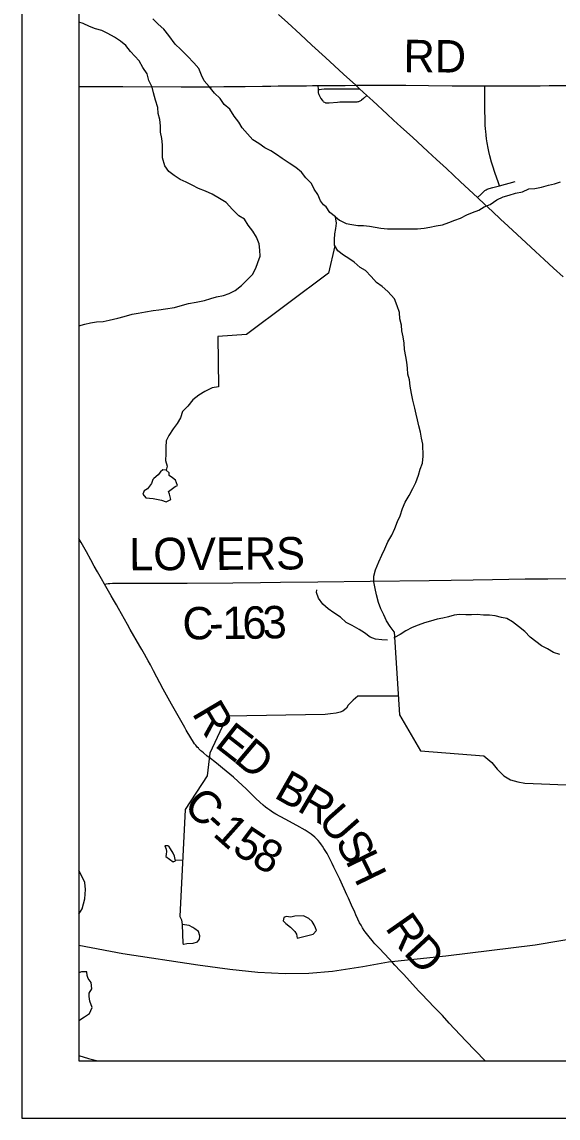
# Model space of a CAD drawing. Extents: x 0 to 34, y 0 to 22.
# Drawn here: x 23.344 to 24.284, y 13.024 to 14.945 of the extents above; entities that cross this region are included whole.
import ezdxf

# ---------------------------------------------------------------- set-up
doc = ezdxf.new("R2010")
doc.units = 0
for name, color, linetype in [('GM_X_Corporation', 7, 'Continuous'), ('GM_X_County_Road', 7, 'Continuous'), ('GM_X_County_Road_Text', 7, 'Continuous'), ('GM_X_Minor_Lake', 7, 'Continuous'), ('GM_X_Minor_River', 7, 'Continuous'), ('GM_X_Rail_Line', 7, 'Continuous'), ('GM_X_State_Route', 7, 'Continuous'), ('GM_X_Township_Road', 7, 'Continuous'), ('GM_X_Township_Road_Text', 7, 'Continuous'), ('SH_Data', 7, 'Continuous')]:
    doc.layers.add(name, color=color, linetype=linetype)

msp = doc.modelspace()

# ---------------------------------------------------------------- linework, layer by layer
at = {"layer": 'GM_X_Corporation'}
msp.add_lwpolyline([(23.4438, 15.6034), (23.4438, 13.1239), (28.8008, 13.1239)], dxfattribs=at)
at = {"layer": 'GM_X_County_Road'}
for points in [[(23.4888, 13.9594), (23.4834, 13.9688), (23.4763, 13.9812), (23.4708, 13.9909), (23.4645, 14.0023), (23.4571, 14.016), (23.4478, 14.0327), (23.4438, 14.0398)], [(23.4888, 13.9594), (23.4916, 13.9601), (23.4949, 13.9607), (23.4982, 13.961), (23.5028, 13.9612), (23.5118, 13.9614), (23.5311, 13.9615), (23.6336, 13.9613), (23.7135, 13.9616), (23.762, 13.9624), (23.7974, 13.9629), (23.8625, 13.9638), (23.9543, 13.9647), (24.0582, 13.9658), (24.1348, 13.9672), (24.1688, 13.968), (24.2264, 13.9689), (24.266, 13.9688), (24.3705, 13.9698)], [(23.966, 13.3259), (23.9629, 13.3292), (23.9599, 13.3326), (23.9585, 13.3342), (23.955, 13.3383), (23.9479, 13.3472), (23.9457, 13.35), (23.9439, 13.3525), (23.941, 13.3571), (23.9384, 13.3618), (23.936, 13.3662), (23.9328, 13.3727), (23.9293, 13.3801), (23.9273, 13.3846), (23.9219, 13.3971), (23.9163, 13.4094), (23.9137, 13.4151), (23.9012, 13.4423), (23.8973, 13.4505), (23.891, 13.4635), (23.8879, 13.4701), (23.8862, 13.4734), (23.8788, 13.4874), (23.8735, 13.4965), (23.871, 13.5003), (23.8693, 13.5028), (23.8664, 13.5066), (23.8635, 13.5102), (23.8611, 13.5127), (23.8573, 13.5164), (23.8511, 13.5217), (23.8459, 13.5252), (23.8407, 13.5285), (23.826, 13.5368), (23.8057, 13.5475), (23.7893, 13.5564), (23.7831, 13.5602), (23.7784, 13.5632), (23.7749, 13.5658), (23.7709, 13.5688), (23.7666, 13.5723), (23.7548, 13.5833), (23.7363, 13.6016), (23.7308, 13.6068), (23.7148, 13.6211), (23.6957, 13.6372), (23.685, 13.6458), (23.6714, 13.6562), (23.6687, 13.6584), (23.6623, 13.6637), (23.6593, 13.6663), (23.6577, 13.6677), (23.6555, 13.6697), (23.6541, 13.671), (23.6533, 13.6719), (23.6513, 13.6741), (23.6487, 13.6772), (23.6467, 13.68), (23.632, 13.7036), (23.6293, 13.7082), (23.6062, 13.7491), (23.5917, 13.7758), (23.5748, 13.8076), (23.569, 13.8183), (23.5652, 13.8252), (23.5621, 13.8306), (23.5586, 13.8368), (23.5539, 13.845), (23.5505, 13.8509), (23.5338, 13.88), (23.5289, 13.8887), (23.513, 13.9168), (23.5094, 13.9233), (23.5046, 13.9318), (23.5003, 13.9393), (23.4932, 13.9516), (23.4888, 13.9594)], [(23.9979, 13.2918), (23.9936, 13.2966), (23.9881, 13.3026), (23.9701, 13.3214), (23.966, 13.3259)], [(24.156, 13.1239), (24.1387, 13.1422), (24.1221, 13.1595), (24.093, 13.1904), (24.0812, 13.2035), (24.077, 13.208), (24.0665, 13.2185), (24.0449, 13.2411), (24.0398, 13.2465), (24.0232, 13.2646), (24.0134, 13.2753), (24.0072, 13.2819), (23.9979, 13.2918)]]:
    msp.add_lwpolyline(points, dxfattribs=at)
at = {"layer": 'GM_X_Minor_Lake'}
for p, q in [((23.5736, 14.1429), (23.571, 14.136)), ((23.5962, 13.4821), (23.6091, 13.4731)), ((23.6248, 13.3629), (23.6261, 13.3299)), ((23.8263, 13.3394), (23.8543, 13.3461))]:
    msp.add_line(p, q, dxfattribs=at)
for points in [[(23.571, 14.136), (23.5639, 14.1269), (23.5579, 14.1234), (23.556, 14.117), (23.561, 14.1106), (23.5742, 14.1095), (23.5883, 14.1066), (23.597, 14.104), (23.6049, 14.1079), (23.6026, 14.1173), (23.6006, 14.1222), (23.6123, 14.131), (23.6164, 14.1326), (23.6133, 14.142), (23.608, 14.1458), (23.6023, 14.1499), (23.6019, 14.1549), (23.5969, 14.1594), (23.5909, 14.1597), (23.5867, 14.1563), (23.583, 14.1513), (23.5751, 14.1448), (23.5736, 14.1429)], [(23.6091, 13.4731), (23.6129, 13.4747), (23.6125, 13.4773), (23.6113, 13.4826), (23.609, 13.4883), (23.6044, 13.4955), (23.6017, 13.5004), (23.5995, 13.5007), (23.5942, 13.5007), (23.5965, 13.4954), (23.5973, 13.4908), (23.5969, 13.4863), (23.5962, 13.4821)], [(23.4438, 13.3814), (23.4497, 13.3907), (23.4541, 13.4082), (23.4555, 13.4245), (23.4539, 13.4366), (23.4485, 13.4491), (23.4438, 13.4578)], [(23.8543, 13.3461), (23.8603, 13.3526), (23.8587, 13.3571), (23.8564, 13.3628), (23.8529, 13.3681), (23.8468, 13.3737), (23.8377, 13.3782), (23.8222, 13.3777), (23.8154, 13.3761), (23.8071, 13.3772), (23.8029, 13.3756), (23.8018, 13.3696), (23.8068, 13.3651), (23.8148, 13.3587), (23.8224, 13.3511), (23.8251, 13.3462), (23.8263, 13.3394)], [(23.6261, 13.3299), (23.6277, 13.3288), (23.633, 13.3296), (23.6443, 13.3304), (23.6519, 13.3328), (23.6552, 13.3373), (23.6556, 13.343), (23.6532, 13.3506), (23.6471, 13.3555), (23.6433, 13.3581), (23.6369, 13.3611), (23.6248, 13.3629)], [(23.4438, 13.1947), (23.4538, 13.2015), (23.4625, 13.2073), (23.4669, 13.2179), (23.4627, 13.2285), (23.4615, 13.2368), (23.4618, 13.2425), (23.4663, 13.2505), (23.4654, 13.2615), (23.4601, 13.2687), (23.4582, 13.2736), (23.4574, 13.28), (23.4483, 13.28), (23.4438, 13.2782)]]:
    msp.add_lwpolyline(points, dxfattribs=at)
at = {"layer": 'GM_X_Minor_River'}
for p, q in [((23.8926, 14.5527), (23.8815, 14.5043)), ((23.8815, 14.5043), (23.7374, 14.3971)), ((23.9966, 13.8758), (24.0057, 13.7306)), ((24.0057, 13.7306), (24.0429, 13.6676)), ((24.0429, 13.6676), (24.1535, 13.6586)), ((24.1535, 13.6586), (24.1676, 13.647)), ((24.1676, 13.647), (24.1771, 13.6353)), ((24.1771, 13.6353), (24.1889, 13.6236)), ((24.1889, 13.6236), (24.2007, 13.6165)), ((24.2007, 13.6165), (24.2132, 13.6132)), ((24.2132, 13.6132), (24.2254, 13.611)), ((24.2254, 13.611), (24.596, 13.596))]:
    msp.add_line(p, q, dxfattribs=at)
for points in [[(23.8725, 14.6243), (23.8676, 14.6316), (23.8626, 14.6422), (23.8565, 14.652), (23.8518, 14.6618), (23.8415, 14.6716), (23.8339, 14.6818), (23.8244, 14.6897), (23.8122, 14.6972), (23.8004, 14.7054), (23.7901, 14.7125), (23.7802, 14.7189), (23.7696, 14.7241), (23.7593, 14.732), (23.7487, 14.7384), (23.7303, 14.7595), (23.7242, 14.7693), (23.7158, 14.7795), (23.7085, 14.7919), (23.6982, 14.8002), (23.6913, 14.8107), (23.6818, 14.8202), (23.6722, 14.8318), (23.6634, 14.8416), (23.6588, 14.8518), (23.6538, 14.8635), (23.6454, 14.8733), (23.634, 14.885), (23.6225, 14.8963), (23.6126, 14.9057), (23.6015, 14.9212), (23.5927, 14.9321), (23.5828, 14.9407), (23.5733, 14.9501)], [(23.7404, 14.5889), (23.7339, 14.5995), (23.7244, 14.6051), (23.7133, 14.616), (23.7022, 14.6284), (23.6901, 14.6356), (23.6775, 14.643), (23.6657, 14.6483), (23.6532, 14.6531), (23.6426, 14.6587), (23.6319, 14.6639), (23.6213, 14.6688), (23.611, 14.6755), (23.6015, 14.683), (23.5942, 14.6928), (23.5903, 14.7065), (23.5906, 14.7163), (23.5902, 14.7296), (23.5893, 14.7406), (23.5866, 14.7519), (23.5869, 14.7629), (23.5856, 14.7739), (23.5829, 14.7845), (23.5824, 14.7951), (23.5782, 14.808), (23.5743, 14.8205), (23.5723, 14.8307), (23.5662, 14.842), (23.5634, 14.8537), (23.5558, 14.8651), (23.5493, 14.8768), (23.534, 14.893), (23.526, 14.9035), (23.5164, 14.9114), (23.5062, 14.9181), (23.4944, 14.9245), (23.4837, 14.9297), (23.4727, 14.9327), (23.4621, 14.9368), (23.4511, 14.942), (23.4438, 14.9443)], [(23.8936, 14.6034), (23.9008, 14.5977), (23.9122, 14.5914), (23.9224, 14.5896), (23.933, 14.5881), (23.9429, 14.5882), (23.9531, 14.5872), (23.9633, 14.585), (23.9732, 14.5835), (23.9846, 14.5825), (23.9944, 14.5825), (24.0054, 14.5823), (24.0167, 14.5823), (24.0273, 14.582), (24.0375, 14.5825), (24.0489, 14.5833), (24.0591, 14.5853), (24.0704, 14.5877), (24.0814, 14.5893), (24.0923, 14.5935), (24.1029, 14.5974), (24.1131, 14.6009), (24.124, 14.6071), (24.1342, 14.6109), (24.1448, 14.6152), (24.1546, 14.6209), (24.1648, 14.6252), (24.1764, 14.6329), (24.1877, 14.6383), (24.1983, 14.6414), (24.2093, 14.6449), (24.2213, 14.6472), (24.2327, 14.6522), (24.2433, 14.6531), (24.255, 14.6555), (24.2674, 14.6586), (24.2776, 14.6613), (24.2882, 14.6644)], [(23.9755, 14.4815), (23.9656, 14.4883), (23.9561, 14.4988), (23.9465, 14.509), (23.937, 14.5146), (23.9267, 14.5236), (23.9172, 14.5304), (23.9077, 14.5364), (23.8978, 14.5439), (23.8921, 14.5537), (23.892, 14.5636), (23.8927, 14.5734), (23.8945, 14.5829), (23.8955, 14.5924), (23.8936, 14.6034), (23.884, 14.6109), (23.8775, 14.6211), (23.8725, 14.6243)], [(23.4438, 14.4124), (23.4541, 14.4153), (23.4639, 14.4177), (23.4745, 14.4193), (23.4862, 14.4201), (23.4968, 14.4221), (23.5119, 14.4256), (23.5233, 14.4288), (23.5372, 14.433), (23.5478, 14.4346), (23.5607, 14.4366), (23.5739, 14.439), (23.5841, 14.4406), (23.5958, 14.4422), (23.6113, 14.4446), (23.6253, 14.4485), (23.6359, 14.4512), (23.6491, 14.454), (23.6642, 14.4564), (23.6748, 14.4599), (23.685, 14.463), (23.6971, 14.4657), (23.7073, 14.4692), (23.7178, 14.4742), (23.7287, 14.4827), (23.7385, 14.4922), (23.7483, 14.5022), (23.7539, 14.5136), (23.7576, 14.5231), (23.7616, 14.5345), (23.7608, 14.5451), (23.7596, 14.5557), (23.7553, 14.5674), (23.7488, 14.5784), (23.7404, 14.5889)], [(23.9832, 13.8954), (23.9782, 13.906), (23.9732, 13.9162), (23.9689, 13.9275), (23.9654, 13.9408), (23.9631, 13.9521), (23.9611, 13.9635), (23.961, 13.9737), (23.9639, 13.9848), (23.9695, 13.9988), (23.9751, 14.0106), (23.9799, 14.0217), (23.9855, 14.0335), (23.9922, 14.0456), (23.9978, 14.0571), (24.0022, 14.0692), (24.0071, 14.0795), (24.0111, 14.0924), (24.016, 14.1031), (24.0231, 14.1149), (24.0294, 14.1271), (24.0343, 14.1377), (24.0391, 14.1503), (24.042, 14.1609), (24.0461, 14.1716), (24.0475, 14.1837), (24.0466, 14.2049), (24.0446, 14.2152), (24.0426, 14.2258), (24.0399, 14.2371), (24.0372, 14.2473), (24.0352, 14.2572), (24.0328, 14.2681), (24.0293, 14.2818), (24.027, 14.2939), (24.0246, 14.3068), (24.0234, 14.3177), (24.0206, 14.3276), (24.0202, 14.3382), (24.019, 14.3484), (24.017, 14.3586), (24.0146, 14.3708), (24.0138, 14.3821), (24.0126, 14.3931), (24.0102, 14.4037), (24.0094, 14.4136), (24.0066, 14.4245), (24.0058, 14.4359), (24.0019, 14.4472), (23.9973, 14.4597), (23.9854, 14.4725), (23.9755, 14.4815)], [(23.7374, 14.3971), (23.6874, 14.3936), (23.6885, 14.3053), (23.6772, 14.3037), (23.6647, 14.2971), (23.6542, 14.291), (23.6436, 14.2826), (23.6347, 14.2715), (23.6256, 14.262), (23.6219, 14.2513), (23.6163, 14.2414), (23.6089, 14.2315), (23.6014, 14.2201), (23.5969, 14.2106), (23.5959, 14.1999), (23.5959, 14.1882), (23.5957, 14.1764), (23.5988, 14.1666), (23.5969, 14.1594)], [(23.985, 13.8613), (23.9747, 13.862), (23.9641, 13.863), (23.9543, 13.8664), (23.9447, 13.8743), (23.9349, 13.8799), (23.9231, 13.887), (23.9124, 13.8926), (23.9025, 13.902), (23.8907, 13.9095), (23.8808, 13.9162), (23.8713, 13.9245), (23.8636, 13.9351), (23.8605, 13.9449), (23.8609, 13.9494)], [(23.9966, 13.8758), (23.9897, 13.8856), (23.9832, 13.8954)], [(24.2872, 13.8363), (24.2762, 13.84), (24.2652, 13.846), (24.2549, 13.8516), (24.245, 13.8588), (24.2351, 13.8666), (24.2256, 13.8764), (24.2145, 13.8854), (24.2039, 13.8937), (24.194, 13.8993), (24.1845, 13.9011), (24.1739, 13.9041), (24.1636, 13.9055), (24.1534, 13.9051), (24.1421, 13.9061), (24.1322, 13.906), (24.122, 13.9056), (24.1114, 13.9063), (24.1016, 13.905), (24.0917, 13.9023), (24.0816, 13.9), (24.0717, 13.898), (24.0604, 13.8949), (24.0498, 13.8918), (24.0389, 13.8875), (24.0283, 13.8836), (24.017, 13.8779), (24.0068, 13.8713), (23.997, 13.8663), (23.9959, 13.8652)], [(24.0036, 13.7632), (23.9331, 13.7631), (23.9245, 13.7562), (23.9192, 13.7508), (23.9158, 13.7474), (23.9128, 13.7421), (23.9065, 13.7367), (23.9019, 13.7351), (23.8948, 13.7332), (23.8849, 13.7324), (23.8755, 13.7311), (23.7037, 13.7283), (23.6731, 13.6632), (23.6689, 13.6237), (23.63, 13.5647), (23.6205, 13.3769), (23.6235, 13.3711), (23.6248, 13.3629)], [(23.6255, 13.4755), (23.6127, 13.4758)]]:
    msp.add_lwpolyline(points, dxfattribs=at)
at = {"layer": 'GM_X_Rail_Line'}
for points in [[(23.4438, 13.3271), (23.521, 13.3121), (23.6525, 13.2925), (23.7082, 13.2847), (23.7576, 13.2795), (23.8057, 13.2772), (23.847, 13.278), (23.8886, 13.2816), (23.9419, 13.2897), (23.9869, 13.2979), (24.0872, 13.3083), (24.2438, 13.3277), (24.4272, 13.3583), (24.6257, 13.3826), (24.6809, 13.3853), (24.7246, 13.3839), (24.7611, 13.3791), (24.7893, 13.3718), (24.8141, 13.3644), (24.8529, 13.3486), (25.2641, 13.1608), (25.3393, 13.1239)], [(23.4438, 13.1333), (23.4604, 13.1282), (23.4767, 13.1241), (23.4775, 13.1239)]]:
    msp.add_lwpolyline(points, dxfattribs=at)
at = {"layer": 'GM_X_State_Route'}
for points in [[(23.794, 14.9577), (23.8101, 14.9431), (23.8316, 14.9233), (23.8523, 14.9044), (23.8762, 14.8826), (23.9077, 14.8536), (23.9294, 14.8338)], [(23.9294, 14.8338), (23.9359, 14.8279), (23.9486, 14.8162), (23.9591, 14.8066), (23.9842, 14.7834), (23.9956, 14.773), (24.0084, 14.7611), (24.0287, 14.7427), (24.0555, 14.7178), (24.0706, 14.7039), (24.0881, 14.6879), (24.1127, 14.6648), (24.1428, 14.637), (24.1558, 14.6248), (24.1689, 14.6126), (24.1831, 14.5993), (24.1963, 14.5871), (24.2123, 14.5722), (24.2282, 14.5575), (24.2445, 14.5425), (24.2597, 14.5284), (24.2761, 14.5134), (24.2928, 14.4979)]]:
    msp.add_lwpolyline(points, dxfattribs=at)
at = {"layer": 'GM_X_Township_Road'}
msp.add_line((24.1811, 14.6579), (24.2087, 14.6653), dxfattribs=at)
for points in [[(23.4438, 14.8317), (23.5208, 14.8316), (23.6232, 14.831), (23.6371, 14.831), (23.6549, 14.8311), (23.6638, 14.8312), (23.6747, 14.8314), (23.6767, 14.8314)], [(23.6767, 14.8314), (23.6978, 14.8316), (23.7353, 14.832), (23.7657, 14.8324), (23.7801, 14.8325), (23.7929, 14.8326), (23.8058, 14.8327), (23.8193, 14.8328), (23.8426, 14.833), (23.8535, 14.8332), (23.8635, 14.8332)], [(23.8635, 14.8332), (23.9104, 14.8335), (23.9294, 14.8338)], [(23.9486, 14.8162), (23.9426, 14.8108), (23.9395, 14.808), (23.9384, 14.8071), (23.9373, 14.8064), (23.9362, 14.8058), (23.9351, 14.8053), (23.9339, 14.805), (23.9327, 14.8047), (23.9312, 14.8045), (23.9277, 14.8043), (23.9241, 14.8042), (23.9141, 14.8042), (23.9054, 14.8042), (23.9014, 14.8041), (23.8974, 14.8038), (23.8824, 14.8024), (23.8809, 14.8023), (23.8796, 14.8023), (23.8787, 14.8024), (23.8777, 14.8025), (23.8768, 14.8027), (23.876, 14.803), (23.8747, 14.8037), (23.8735, 14.8045), (23.8728, 14.8051), (23.8712, 14.8069), (23.8679, 14.8113), (23.8661, 14.8145), (23.8649, 14.8174), (23.8644, 14.8189), (23.8641, 14.8203), (23.8639, 14.8219), (23.8638, 14.8234), (23.8637, 14.8264), (23.8635, 14.8332)], [(23.9294, 14.8338), (23.971, 14.8343), (23.984, 14.8343), (24.0173, 14.834), (24.0567, 14.8335), (24.0981, 14.8331), (24.1556, 14.8331)], [(24.1556, 14.8331), (24.1863, 14.8331), (24.2527, 14.8331), (24.2682, 14.8332), (24.2875, 14.8333), (24.311, 14.8337), (24.3455, 14.834)], [(24.1811, 14.6579), (24.1794, 14.6629), (24.1731, 14.681), (24.1695, 14.6922), (24.1674, 14.6991), (24.1643, 14.71), (24.1624, 14.7179), (24.1612, 14.7239), (24.1597, 14.7329), (24.1586, 14.74), (24.1578, 14.7467), (24.1572, 14.7532), (24.1569, 14.7569), (24.1564, 14.7647), (24.1561, 14.7692), (24.156, 14.7714), (24.156, 14.775), (24.1558, 14.7898), (24.1556, 14.8295), (24.1556, 14.8331)], [(23.8637, 14.8264), (23.8654, 14.8266), (23.8692, 14.8271), (23.874, 14.8275), (23.8789, 14.8277), (23.8852, 14.8278), (23.9064, 14.8276), (23.924, 14.8276), (23.9359, 14.8279)], [(24.1428, 14.637), (24.1483, 14.6427), (24.1543, 14.6482), (24.1558, 14.6494), (24.1579, 14.6508), (24.1595, 14.6517), (24.1611, 14.6524), (24.1634, 14.6532), (24.1695, 14.6549), (24.1811, 14.6579)]]:
    msp.add_lwpolyline(points, dxfattribs=at)
at = {"layer": 'SH_Data'}
for p, q in [((23.3438, 20.0239), (23.3438, 13.0239)), ((23.4438, 19.9239), (23.4438, 13.1239)), ((23.4438, 13.1239), (30.2438, 13.1239)), ((23.4438, 13.1239), (23.4438, 13.1239)), ((23.3438, 13.0239), (30.3438, 13.0239))]:
    msp.add_line(p, q, dxfattribs=at)

# ---------------------------------------------------------------- texts
at = {"layer": 'GM_X_County_Road_Text'}
for s, height, rotation, p in [('LOVERS', 0.05682, 0.3519, (23.5321, 13.9836)), ('C', 0.0568, 0.5816, (23.6256, 13.8625)), ('1', 0.0568, 0.6491, (23.6957, 13.8632)), ('6', 0.0568, 0.833, (23.7309, 13.8636)), ('3', 0.0568, 1.3824, (23.7665, 13.8641)), ('-', 0.0568, 0.5858, (23.6723, 13.863)), ('R', 0.0568, 300.6231, (23.641, 13.7334)), ('E', 0.0568, 322.0428, (23.6798, 13.6762)), ('D', 0.0568, 319.8717, (23.7129, 13.6504)), ('B', 0.0568, 330.3824, (23.7839, 13.5866)), ('R', 0.0568, 329.5885, (23.8243, 13.5636)), ('C', 0.0568, 317.982, (23.6244, 13.567)), ('U', 0.0568, 311.3682, (23.8608, 13.543)), ('-', 0.0568, 318.0314, (23.6591, 13.5358)), ('1', 0.0568, 318.3042, (23.6767, 13.52)), ('5', 0.0568, 326.6636, (23.71, 13.4912)), ('S', 0.0568, 299.0648, (23.892, 13.5081)), ('8', 0.0568, 331.7215, (23.7439, 13.4691)), ('H', 0.0568, 295.9916, (23.9103, 13.4753)), ('R', 0.0568, 304.9891, (23.9795, 13.3571)), ('D', 0.0568, 312.6175, (24.0114, 13.3125))]:
    msp.add_text(s, height=height, rotation=rotation, dxfattribs=at).set_placement(p)
at = {"layer": 'GM_X_Township_Road_Text'}
msp.add_text('RD', height=0.05682, rotation=359.5089, dxfattribs=at).set_placement((24.0127, 14.8569))

doc.saveas('drawing.dxf')
